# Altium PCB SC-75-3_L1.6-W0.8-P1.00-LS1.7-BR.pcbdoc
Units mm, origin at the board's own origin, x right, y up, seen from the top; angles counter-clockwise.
Board outline 14.57 x 14.34 mm, 2 copper layers (Top Layer, Bottom Layer), stack 0 mm thick; 1 components, 0 nets, 3 pads, 0 vias.
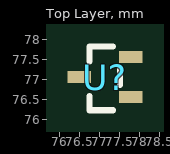
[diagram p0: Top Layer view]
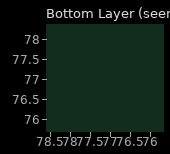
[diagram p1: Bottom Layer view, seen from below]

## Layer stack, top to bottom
Top Layer: signal copper (thickness not stored)
Bottom Layer: signal copper (thickness not stored)

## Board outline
84.42,69.85 69.85,69.85 69.85,84.19 84.42,84.19

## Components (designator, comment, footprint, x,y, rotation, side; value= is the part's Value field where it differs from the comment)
U? "" SC-75-3_L1.6-W0.8-P1.00-LS1.7-BR 77.135,77.05 r0 top

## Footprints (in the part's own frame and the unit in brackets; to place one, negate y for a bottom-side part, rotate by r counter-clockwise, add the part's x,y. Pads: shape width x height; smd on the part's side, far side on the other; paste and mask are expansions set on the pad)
SC-75-3_L1.6-W0.8-P1.00-LS1.7-BR [mm]
  rect 0.585x0.301 smd: 1(0.643,-0.5) 2(0.643,0.5) 3(-0.643,0)
  silkscreen extent -0.38,-0.83 0.38,0.76

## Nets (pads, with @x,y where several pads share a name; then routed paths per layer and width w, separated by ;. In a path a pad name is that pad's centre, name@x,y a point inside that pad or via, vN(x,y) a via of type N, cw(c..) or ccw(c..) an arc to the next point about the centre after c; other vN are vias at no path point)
pads on no net: U?.1 U?.2 U?.3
